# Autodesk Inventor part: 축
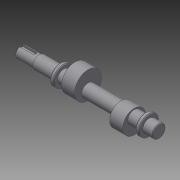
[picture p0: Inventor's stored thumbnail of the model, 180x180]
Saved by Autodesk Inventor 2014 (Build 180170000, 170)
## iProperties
Created: 2014-12
Part Number: 축
Material: 일반
Document SubType Name: Modeling
Designer: Owner
Density: 1 g/cm^3
Appearance: 기본값
Author: Owner
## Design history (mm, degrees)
sketch "스케치1"
  geometry: L1 (-90, 0)-(90, 0); L2 (-90, 0)-(-90, 7.5); L3 (-90, 7.5)-(-66, 7.5); L4 (-66, 7.5)-(-66, 8.5); L5 (-66, 8.5)-(-39, 8.5); L6 (-39, 8.5)-(-39, 13); L7 (-39, 13)-(-34, 13); L8 (-34, 13)-(-34, 8.5); L9 (-34, 8.5)-(72, 8.5); L10 (72, 8.5)-(72, 13); L11 (72, 13)-(77, 13); L12 (77, 13)-(77, 8.5); L13 (77, 8.5)-(90, 8.5); L14 (90, 8.5)-(90, 0); 2 further points
  constraints: 28 end point, 11 parallel, 6 horizontal alignment, 5 vertical alignment, 2 perpendicular, 1 coincident, 1 collinear, 1 horizontal, 1 midpoint
  dimensions: "d0" = 180 distance of L1.start L1.end; "d1" = 17 diameter of L13 L1; "d2" = 26 diameter of L11 L1; "d3" = 17 diameter of L9 L1; "d4" = 15 diameter of L3 L1; "d5" = 26 diameter of L7 L1; "d6" = 17 diameter of L5 L1; "d7" = 24 distance of L2.end L3.end; "d8" = 27 distance of L4.end L5.end; "d9" = 5 distance of L6.end L7.end; "d10" = 13 distance of L12.end L13.end
revolve "회전1" sketch "스케치1" stored, may be unused: angle "d11" = 90 deg
node "작업 평면1"
sketch "스케치2"
  geometry: C1 r 17.5 at (-6, 0); 1 further point
  constraints: 1 centre point, 1 horizontal alignment
  dimensions: "d13" = 35 diameter of C1; "d14" = 6 distance of point (0, 0) C1.centre
extrude "돌출1" join sketch "스케치2" distance "d15" = 17; taper "d16" = 0 deg
node "작업 평면2"
sketch "스케치3"
  geometry: C1 r 15 at (-5, 0); 1 further point
  constraints: 1 centre point, 1 horizontal alignment
  dimensions: "d18" = 30 diameter of C1; "d19" = 5 distance of C1.centre point (0, 0)
extrude "돌출2" join sketch "스케치3" distance "d20" = 17; taper "d21" = 0 deg
chamfer "모따기1" distance "d22" = 1; stored, may be unused: second distance "d23" = 2, angle "d24" = 45 deg
node "작업 평면3"
sketch "스케치4"
  geometry: L1 (-12, -6.5)-(-12, 6.5) reference; L2 (-12, 2.5)-(5.5, 2.5); L3 (5.5, -2.5)-(-12, -2.5); L4 (-12, -2.5)-(-12, 2.5); A1 r 2.5 centre (5.5, 0) between (5.5, -2.5) and (5.5, 2.5); 3 further points
  constraints: 6 end point, 4 horizontal alignment, 3 point on circle, 2 midpoint, 1 centre point, 1 horizontal, 1 parallel, 1 vertical, 1 vertical alignment
  dimensions: "d26" = 20 distance from line of point (8, 0) L4; "d27" = 5 distance of L3.end L2.start; "d28" = 2.5 radius of A1
extrude "돌출3" cut sketch "스케치4" distance "d29" = 3; taper "d30" = 0 deg
node "솔리드1"
other parameters: "d12" = 14.5, "d17" = 14.5
